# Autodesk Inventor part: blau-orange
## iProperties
Created: 2004-10
Part Number: blau-orange
Document SubType Name: Modeling
Designer: sahrens
Manufacturer: Standard
Standards Organization: Custom
Author: sahrens
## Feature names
1. Extrusion1
2. Rundung2 [Fillet]
